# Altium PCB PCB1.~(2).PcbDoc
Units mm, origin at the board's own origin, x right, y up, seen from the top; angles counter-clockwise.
Board outline 21.72 x 11.94 mm, 2 copper layers (Top Layer, Bottom Layer); 1 components, 0 nets, 16 pads, 0 vias.
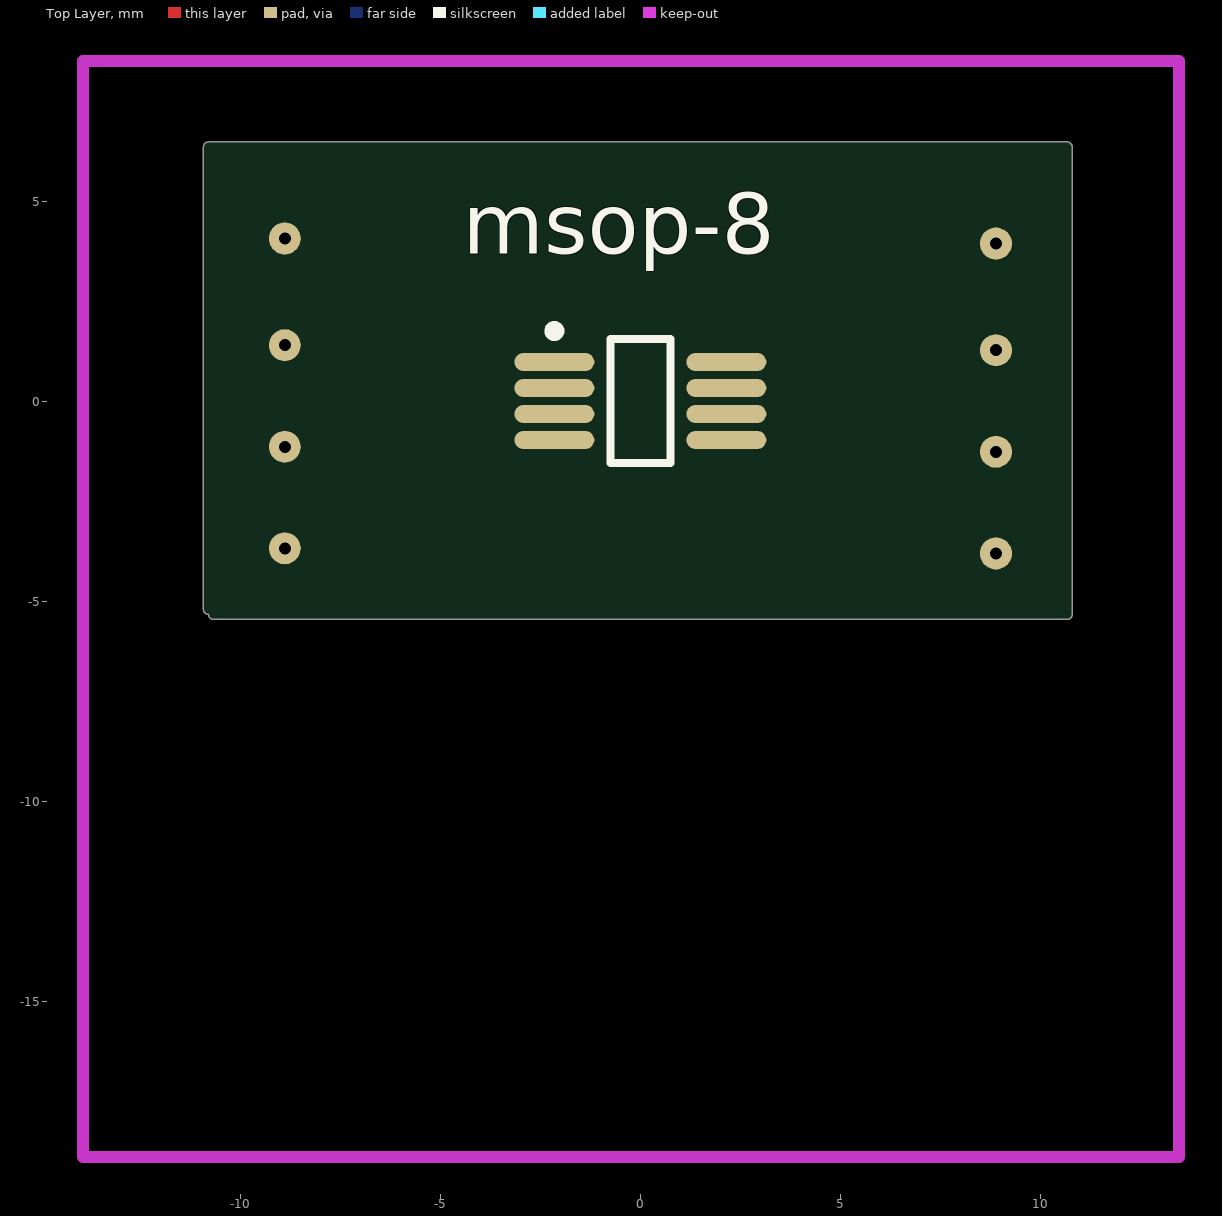
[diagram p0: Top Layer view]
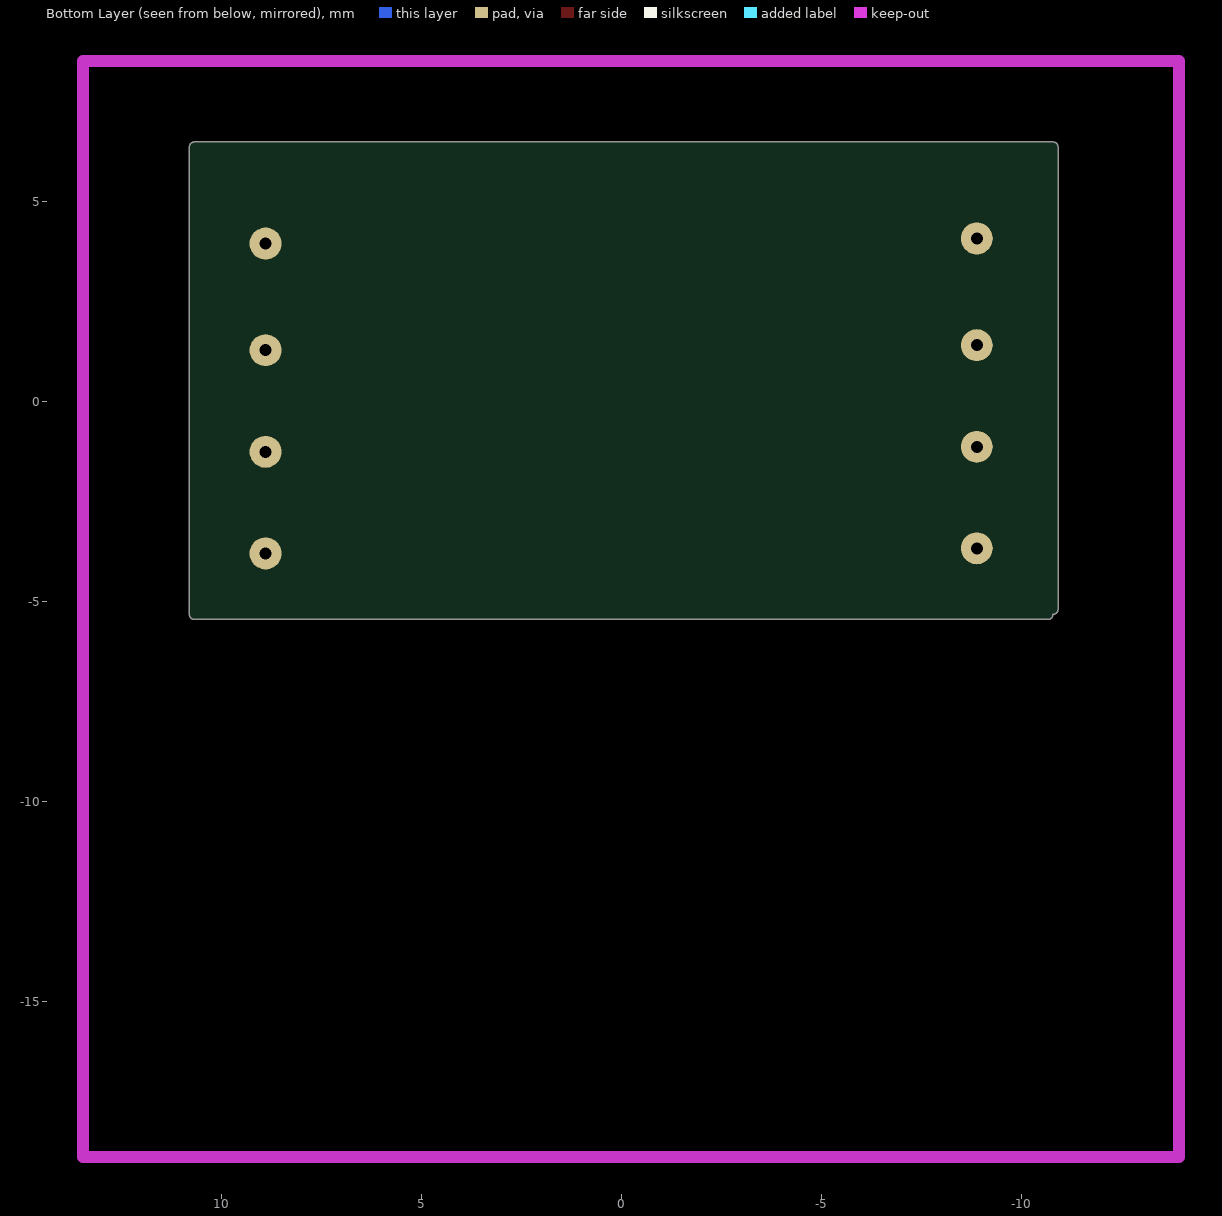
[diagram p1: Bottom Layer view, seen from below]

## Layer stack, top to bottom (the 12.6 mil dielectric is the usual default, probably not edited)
Top Solder: solder mask 0.0102, Solder Resist, Dk 3.5
Top Layer: signal copper 0.0356
Dielectric 1: dielectric 0.32, FR-4, Dk 4.8
Bottom Layer: signal copper 0.0356
Bottom Solder: solder mask 0.0102, Solder Resist, Dk 3.5

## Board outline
-10.795,-5.334 cw(c-10.795,-5.207) -10.922,-5.207 -10.922,6.35 cw(c-10.795,6.35) -10.795,6.477 10.668,6.477 cw(c10.668,6.35) 10.795,6.35 10.795,-5.334 cw(c10.668,-5.334) 10.668,-5.461 -10.668,-5.461 cw(c-10.668,-5.334)

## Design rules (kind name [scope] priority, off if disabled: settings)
Clearance [All] p1: gap=0.5
PolygonConnect [All] p1: connectstyle=Relief reliefconductorwidth=0.254 reliefentries=4 polygonreliefangle="90 Angle" airgapwidth=0.254
RoutingVias [All] p1: holewidth=0.6 width=1 viastyle="Through Hole" minholewidth=0.711 minwidth=1.27 maxholewidth=0.711 maxwidth=1.27
SolderMaskExpansion [All] p1: expansion=0.102
Width [All] p1: maxlimit=0.5 minlimit=0.5 preferedwidth=0.5
30 further rules are at their usual default settings.

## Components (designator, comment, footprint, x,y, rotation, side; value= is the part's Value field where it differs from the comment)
msop-8 "Comment" MSOP-8 0,0 r0 top

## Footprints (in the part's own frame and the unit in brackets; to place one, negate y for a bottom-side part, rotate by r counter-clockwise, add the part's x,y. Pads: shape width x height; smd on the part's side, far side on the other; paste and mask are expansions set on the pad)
MSOP-8 [mm] "TSOP, 8-Leads, Body 3x3mm, Pitch 0.65mm, IPC Low Density"
  oval 2x0.45 smd: 1(-2.15,0.975) 2(-2.15,0.325) 3(-2.15,-0.325) 4(-2.15,-0.975) 5(2.15,-0.975) 6(2.15,-0.325) 7(2.15,0.325) 8(2.15,0.975)
  silkscreen extent -2.27,-1.55 0.75,1.87, body extent -1.55,-1.55 1.55,1.55, height 1.1

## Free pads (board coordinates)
  round 0.8 hole 0.3: 0(-8.89,-3.683) 0(-8.89,-1.143) 0(-8.89,1.397) 0(-8.89,4.064) 0(8.89,-3.81) 0(8.89,-1.27) 0(8.89,1.27) 0(8.89,3.937)

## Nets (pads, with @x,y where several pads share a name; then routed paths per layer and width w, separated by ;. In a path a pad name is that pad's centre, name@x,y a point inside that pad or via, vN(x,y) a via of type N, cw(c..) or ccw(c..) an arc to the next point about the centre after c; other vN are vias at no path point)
pads on no net: msop-8.1 msop-8.2 msop-8.3 msop-8.4 msop-8.5 msop-8.6 msop-8.7 msop-8.8

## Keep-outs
Keep-Out Layer:
  lines w0.3: -13.94,-18.893 13.46,-18.893 13.46,8.507 -13.94,8.507 -13.94,-18.893

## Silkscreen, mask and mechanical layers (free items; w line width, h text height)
Mechanical 1:
  lines w0.254: -10.795,-5.207 -10.795,6.35 10.668,6.35 10.668,-5.334 -10.668,-5.334 -10.795,-5.207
